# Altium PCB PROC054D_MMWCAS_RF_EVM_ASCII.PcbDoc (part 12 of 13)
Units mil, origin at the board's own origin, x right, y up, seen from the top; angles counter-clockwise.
Board outline 6299.21 x 5370.07 mil, 8 copper layers (L1 TOP, L2 GND, L3 SIGNAL 1, L4 GND, L5 SIGNAL 2, L6 SIGNAL 3, L7 GND, L8 BOTTOM), stack 53.5 mil thick; 775 components, 552 nets, 2648 pads, 7845 vias.
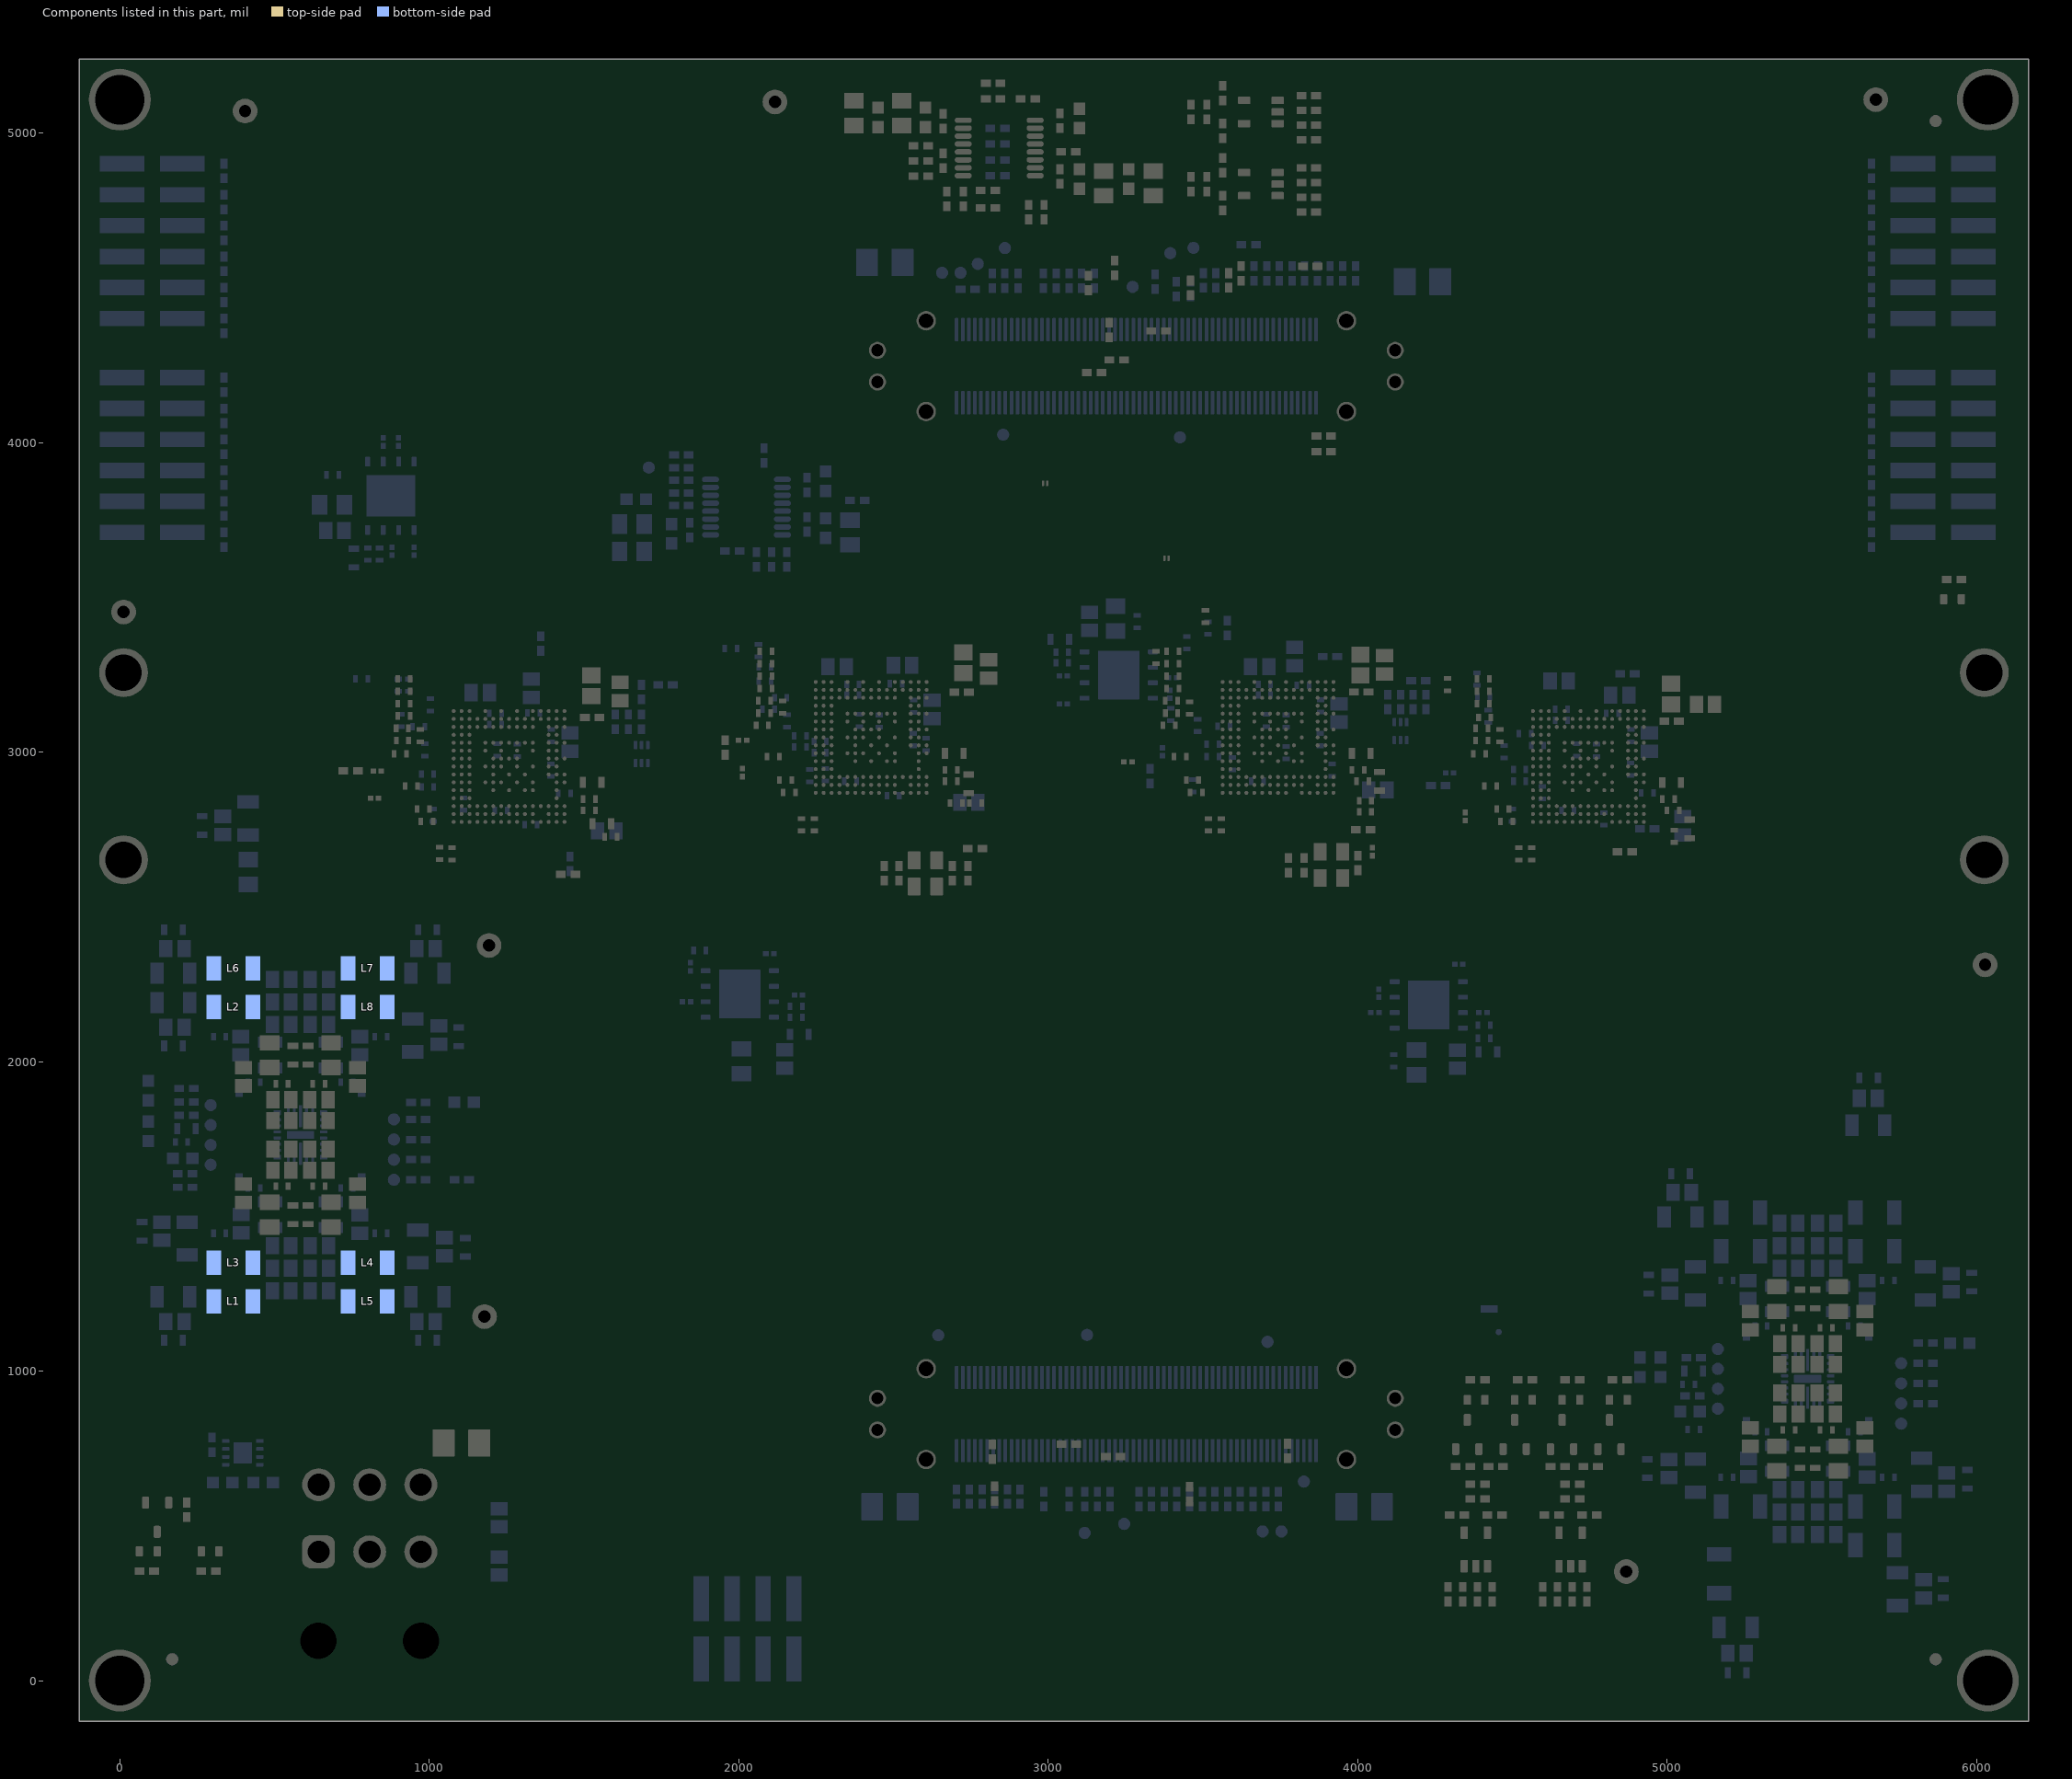
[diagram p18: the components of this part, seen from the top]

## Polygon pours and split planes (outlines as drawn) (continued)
AWR_4_1V2_FILT on L8 BOTTOM "L8_BOTTOM_AWR_4_1V2_FILT_P29790" (solid, remove dead copper, pour order 29790): 19 vertices, not listed, extent -131.11,1296.94 332.13,3060.36
AWR_4_1V8_FILT on L8 BOTTOM "L8_BOTTOM_AWR_4_1V8_FILT_P29702" (solid, remove dead copper, pour order 29702): 1314.48,3068.75 1283.95,3099.27 1283.95,3185.88 1297.79,3199.72 1357.07,3199.72 1360.98,3195.82 1360.98,3156.42 1356.01,3151.45 1340.03,3151.45 1328.67,3140.09 1328.67,3082.94 1316.61,3070.88
AWR_3_1V8_FILT on L8 BOTTOM "L8_BOTTOM_AWR_3_1V8_FILT_P29703" (solid, remove dead copper, pour order 29703): 3799.3,3157.94 3799.3,3160.31 3764.59,3195.02 3764.59,3296.99 3768.63,3301.03 3817.76,3301.03 3824.31,3294.48 3824.31,3174.4 3808.57,3158.65
LMK2_3V3 on L8 BOTTOM "L8_BOTTOM_LMK2_3V3_P29704" (solid, remove dead copper, pour order 29704): 1985.94,3661.24 2019.56,3661.24 2021.37,3659.44 2021.37,3627.32 2032.47,3616.21 2066.39,3616.21 2070.9,3611.71 2070.9,3549.27 2068.19,3546.56 2002.15,3546.56 1982.34,3566.38 1982.34,3657.85 1985.51,3661.02
PMIC1_SW_B1 on L8 BOTTOM "L8_BOTTOM_PMIC1_SW_B1_P29708" (solid, remove dead copper, pour order 29708): 564.74,1621.53 540.48,1597.27 540.48,1534.8 531.2,1525.51 446.86,1525.51 441.43,1530.95 441.43,1600.06 444.98,1603.62 526.25,1603.62 564.74,1642.11
PMIC2_SW_B3 on L8 BOTTOM "L8_BOTTOM_PMIC2_SW_B3_P29711" (solid, remove dead copper, pour order 29711): 5435.47,1116.54 5411.21,1140.8 5411.21,1203.27 5401.92,1212.56 5317.59,1212.56 5312.15,1207.12 5312.15,1138 5315.71,1134.45 5396.98,1134.45 5435.47,1095.96
PMIC1_SW_B3 on L8 BOTTOM "L8_BOTTOM_PMIC1_SW_B3_P29709" (solid, remove dead copper, pour order 29709): 564.74,1904.39 540.48,1928.65 540.48,1991.13 531.2,2000.41 446.86,2000.41 441.43,1994.97 441.43,1925.86 444.98,1922.3 526.25,1922.3 564.74,1883.81
PMIC2_SW_B1 on L8 BOTTOM "L8_BOTTOM_PMIC2_SW_B1_P29707" (solid, remove dead copper, pour order 29707): 5435.47,833.68 5411.21,809.41 5411.21,746.94 5401.92,737.66 5317.59,737.66 5312.15,743.09 5312.15,812.21 5315.71,815.77 5396.98,815.77 5435.47,854.26
SYSTEM_3V3 on L8 BOTTOM "L8_BOTTOM_SYSTEM_3V3_P29713" (solid, remove dead copper, pour order 29713): 4119.08,1929.88 4150.24,1961.04 4150.24,1978.85 4161.13,1989.74 4225.69,1989.74 4230.89,1984.54 4230.89,1919.98 4211.1,1900.19 4127.03,1900.19 4119.08,1908.13
SYSTEM_3V3 on L8 BOTTOM "L8_BOTTOM_SYSTEM_3V3_P29714" (solid, remove dead copper, pour order 29714): 1655.67,3304.32 1655.67,3252.4 1673.06,3235.01 1673.06,3202.27 1676.13,3199.2 1751.58,3199.2 1757.72,3205.34 1757.72,3267.24 1716.4,3308.55 1659.81,3308.55 1655.72,3304.45
GND on L8 BOTTOM "L8_BOTTOM_GND_P29716" (solid, remove dead copper, pour order 29716): 2520.71,3233.05 2536.96,3249.29 2536.96,3308.95 2546.24,3318.24 2546.24,3337.25 2562.13,3353.13 2624.56,3353.13 2644,3333.69 2644,3286.65 2635.37,3278.02 2604.61,3278.02 2583.1,3256.51 2583.1,3235.11 2557,3209.01 2520.5,3209.01
AWR_1_1V0_RF2_FILT on L8 BOTTOM "L8_BOTTOM_AWR_1_1V0_RF2_FILT_P29722" (solid, remove dead copper, pour order 29722): 2575.22,3152.32 2566.3,3143.41 2518.78,3143.41 2509.79,3152.4 2509.79,3178.83 2528.38,3197.42 2565.14,3197.42 2593.02,3225.31 2593.02,3244.09 2611.23,3262.29 2666.34,3262.29 2672.43,3256.19 2672.43,3162.3 2662.35,3152.22
GND on L8 BOTTOM "L8_BOTTOM_GND_P29723" (solid, remove dead copper, pour order 29723): 19 vertices, not listed, extent 4830.85,3112.64 4957.73,3269.52
GND on L8 BOTTOM "L8_BOTTOM_GND_P29718" (solid, remove dead copper, pour order 29718): 17 vertices, not listed, extent 324.94,1863.73 435.27,2042.6
GND on L8 BOTTOM "L8_BOTTOM_GND_P29724" (solid, remove dead copper, pour order 29724): 55.37,1459.42 253.34,1459.39 262.11,1468.17 262.11,1516.41 251.59,1526.93 60.99,1526.93 51.3,1517.25 51.3,1463.49
GND on L8 BOTTOM "L8_BOTTOM_GND_P29726" (solid, remove dead copper, pour order 29726): 2310.48,3305.51 2310.48,3241.04 2325.47,3226.05 2341.84,3226.05 2350.84,3217.05 2350.84,3172.19 2241.17,3172.19 2214.62,3198.73 2214.62,3269.85 2259.77,3315 2300.99,3315
GND on L8 BOTTOM "L8_BOTTOM_GND_P29727" (solid, remove dead copper, pour order 29727): 1156.54,3219.67 1156.54,3162.35 1180.32,3138.57 1200.5,3138.57 1202.77,3136.3 1202.77,3076.8 1201.25,3075.29 1104.24,3075.29 1056.16,3123.38 1056.16,3167.32 1080.46,3191.62 1082.27,3191.62 1114.17,3223.53 1152.74,3223.53 1156.46,3219.81
GND on L8 BOTTOM "L8_BOTTOM_GND_P29728" (solid, remove dead copper, pour order 29728): 2743.43,2912.56 2743.43,2973.73 2774.02,3004.31 2793.61,3004.31 2827.53,2970.38 2827.53,2822.73 2808.42,2803.61 2753.95,2803.61 2743.42,2814.15 2743.42,2911.89
GND on L8 BOTTOM "L8_BOTTOM_GND_P29729" (solid, remove dead copper, pour order 29729): 5125.26,693.18 4922.11,693.06 4905.82,709.34 4905.82,748.12 4924.74,767.04 5112.73,767.04 5130.98,748.79 5130.98,698.9
GND on L8 BOTTOM "L8_BOTTOM_GND_P29730" (solid, remove dead copper, pour order 29730): 4049.36,427.21 4120.73,427.22 4132.64,439.13 4132.64,594.57 4120.07,607.14 4041.41,607.14 4036.71,602.44 4036.71,439.87
GND on L8 BOTTOM "L8_BOTTOM_GND_P29731" (solid, remove dead copper, pour order 29731): 2304.82,524.41 2304.82,603.47 2316.8,615.44 2463.57,615.44 2471.61,607.41 2471.61,519.68 2462.83,510.9 2318.33,510.9
GND on L8 BOTTOM "L8_BOTTOM_GND_P29733" (solid, remove dead copper, pour order 29733): 4644.68,3257.81 4644.68,3093.35 4639.57,3088.24 4553.73,3088.24 4533.76,3108.21 4533.95,3108.4 4533.95,3244.72 4557.27,3268.04 4634.41,3268.04 4644.52,3257.92
GND on L8 BOTTOM "L8_BOTTOM_GND_P29735" (solid, remove dead copper, pour order 29735): 5706.74,287.57 5904.93,287.65 5920.47,272.11 5920.47,228.75 5879.89,188.17 5714.78,188.17 5700.3,202.64 5700.3,281.13
QSPI_FLASH_3V3_3 on L8 BOTTOM "L8_BOTTOM_QSPI_FLASH_3V3_3_P29736" (solid, remove dead copper, pour order 29736): 17 vertices, not listed, extent 3053.43,3275.51 3300.68,3418.57
GND on L8 BOTTOM "L8_BOTTOM_GND_P29737" (solid, remove dead copper, pour order 29737): 251.93,2771.63 429.87,2771.53 457.14,2798.8 457.14,2867.2 450.2,2874.13 266.15,2874.13 239.05,2847.04 239.05,2784.52
GND on L8 BOTTOM "L8_BOTTOM_GND_P29738" (solid, remove dead copper, pour order 29738): 5234.36,197.62 5234.36,11.78 5254.9,-8.76 5315.01,-8.76 5336.05,12.28 5336.05,193.94 5320.82,209.17 5245.78,209.17 5234.47,197.86
GND on L8 BOTTOM "L8_BOTTOM_GND_P29740" (solid, remove dead copper, pour order 29740): 1136.85,1409.74 938.77,1409.74 917.18,1431.33 917.18,1495.24 932,1510.05 1113.99,1510.05 1147.98,1476.06 1147.98,1420.75 1137.01,1409.79
GND on L8 BOTTOM "L8_BOTTOM_GND_P29741" (solid, remove dead copper, pour order 29741): 4920.12,1273.11 5110.12,1273.11 5139.01,1244.22 5139.01,1186.07 5125.3,1172.37 4930.49,1172.37 4910.12,1192.74 4910.12,1263.22 4919.64,1272.74
GND on L8 BOTTOM "L8_BOTTOM_GND_P29742" (solid, remove dead copper, pour order 29742): 169.84,1088.49 169.83,1259.99 149.91,1279.91 67.74,1279.91 56.63,1268.79 56.63,1089.92 75.84,1070.71 152.06,1070.71
GND on L8 BOTTOM "L8_BOTTOM_GND_P29743" (solid, remove dead copper, pour order 29743): 997.21,1077.96 996.89,1266.04 1009.07,1278.22 1099.69,1278.22 1110.42,1267.28 1110.45,1076.9 1104.26,1070.71 1004.45,1070.71
GND on L8 BOTTOM "L8_BOTTOM_GND_P29744" (solid, remove dead copper, pour order 29744): 5040.56,1660.15 5040.56,1460.89 5036.7,1457.04 4930.05,1457.04 4927.35,1459.74 4927.35,1661.16 4933.54,1667.36 5033.35,1667.36
GND on L8 BOTTOM "L8_BOTTOM_GND_P29745" (solid, remove dead copper, pour order 29745): 997.84,2245.26 1005.7,2237.4 1102.59,2237.4 1110.45,2245.26 1110.45,2449.02 1104.26,2455.21 1004.45,2455.21 997.21,2447.97
AWR_1_1V8_FILT on L8 BOTTOM "L8_BOTTOM_AWR_1_1V8_FILT_P29746" (solid, remove dead copper, pour order 29746): 332.13,2222.83 332.13,2138.87 275.33,2082.08 275.33,2041.53 262.7,2028.89 196.29,2028.89 185.13,2040.06 185.13,2216.65 197.47,2228.99 326.01,2228.99 332.08,2222.91
GND on L8 BOTTOM "L8_BOTTOM_GND_P29747" (solid, remove dead copper, pour order 29747): 5643.31,1749.23 5643.31,1960.96 5621.7,1982.57 5556.19,1982.57 5536.6,1962.98 5536.6,1760.04 5555.51,1741.13 5635.11,1741.13 5642.94,1748.96
GND on L8 BOTTOM "L8_BOTTOM_GND_P29748" (solid, remove dead copper, pour order 29748): 907.32,1966.28 896.53,1977.07 896.53,2065.22 910.15,2078.84 1113.28,2078.2 1122.53,2068.95 1122.53,1974.86 1113.96,1966.28
LMK2_3V3 on L8 BOTTOM "L8_BOTTOM_LMK2_3V3_P29734" (solid, remove dead copper, pour order 29734): 2207.97,3730.27 2385.87,3730.27 2455.01,3661.14 2455.01,3649.75 2447.16,3641.91 2227.17,3641.91 2194.37,3674.71 2194.37,3717.72 2206.87,3730.22
AWR_4_1V8_FILT on L8 BOTTOM "L8_BOTTOM_AWR_4_1V8_FILT_P29749" (solid, remove dead copper, pour order 29749): 332.13,2341.49 311.01,2362.61 311.01,2403.27 266.74,2447.53 196.29,2447.53 185.13,2436.37 185.13,2259.78 197.47,2247.44 326.01,2247.44 332.08,2253.52
QSPI_FLASH_3V3_2 on L8 BOTTOM "L8_BOTTOM_QSPI_FLASH_3V3_2_P29739" (solid, remove dead copper, pour order 29739): 4108.15,2009.8 4095.5,2022.45 4095.51,2029.36 4128.41,2062.26 4270.24,2062.26 4329.98,2122 4361.68,2122 4372.82,2133.14 4400.06,2133.14 4403.51,2129.69 4403.51,2015.02 4398.28,2009.8
QSPI_FLASH_3V3_4 on L8 BOTTOM "L8_BOTTOM_QSPI_FLASH_3V3_4_P29750" (solid, remove dead copper, pour order 29750): 696.84,3909.9 704.45,3917.51 762.42,3917.51 774.97,3905.14 774.97,3769.35 813.86,3730.46 813.86,3705.83 852.74,3666.95 852.74,3652.82 841.38,3641.45 729.6,3641.45 696.84,3674.22
GND on L8 BOTTOM "L8_BOTTOM_GND_P29751" (solid, remove dead copper, pour order 29751): 5774.37,1277.94 6003.39,1278.01 6019.4,1261.99 6019.4,1196.69 5990.33,1167.61 5777,1167.61 5757.35,1187.26 5757.35,1260.92
SYSTEM_1V8 on L8 BOTTOM "L8_BOTTOM_SYSTEM_1V8_P29752" (solid, remove dead copper, pour order 29752): 447.57,2756.32 260.56,2756.58 244.13,2740.14 244.13,2676.83 312.92,2608.04 442.59,2608.04 452.18,2617.63 452.18,2751.71
QSPI_FLASH_3V3_1 on L8 BOTTOM "L8_BOTTOM_QSPI_FLASH_3V3_1_P29753" (solid, remove dead copper, pour order 29753): 1905.12,2085.04 1890.62,2070.54 1890.62,2024.38 1901.01,2013.47 2175.27,2013.47 2178.49,2016.69 2178.49,2185.59 2173.48,2190.6 2156.66,2190.6 2132.68,2166.63 2107.28,2166.63 2094.75,2154.1 2094.75,2119.75 2060.04,2085.04
AWR_1_1V2_FILT on L8 BOTTOM "L8_BOTTOM_AWR_1_1V2_FILT_P29754" (solid, remove dead copper, pour order 29754): 332.08,1272.41 332.17,1109.48 301.07,1078.39 196.29,1078.39 185.13,1089.56 185.13,1266.14 197.47,1278.48 326.01,1278.48
GND on L8 BOTTOM "L8_BOTTOM_GND_P29755" (solid, remove dead copper, pour order 29755): 5990.27,651.02 5799.61,650.95 5780.88,669.68 5780.88,783.52 5792.5,795.15 5952.19,795.15 5993.37,753.96 5993.37,654.12
GND on L8 BOTTOM "L8_BOTTOM_GND_P29756" (solid, remove dead copper, pour order 29756): 19 vertices, not listed, extent 2371.03,2979.69 2664.08,3136.04
GND on L8 BOTTOM "L8_BOTTOM_GND_P29758" (solid, remove dead copper, pour order 29758): 24 vertices, not listed, extent 5401.32,434.32 5506.97,814.79
GND on L8 BOTTOM "L8_BOTTOM_GND_P29759" (solid, remove dead copper, pour order 29759): 24 vertices, not listed, extent 5401.32,1135.43 5506.97,1515.89
GND on L8 BOTTOM "L8_BOTTOM_GND_P29761" (solid, remove dead copper, pour order 29761): 24 vertices, not listed, extent 530.59,1222.18 636.24,1602.64
AWR_1_1V0_RF1_FILT on L8 BOTTOM "L8_BOTTOM_AWR_1_1V0_RF1_FILT_P29762" (solid, remove dead copper, pour order 29762): 841.37,1393.48 1188.05,1393.48 1196.55,1384.98 1196.55,1304.55 1188.94,1296.94 841.07,1296.94 835,1303.01 834.95,1387.06
AWR_2_1V0_RF2_FILT on L8 BOTTOM "L8_BOTTOM_AWR_2_1V0_RF2_FILT_P29763" (solid, remove dead copper, pour order 29763): 5741.9,635.42 5985.12,635.42 5990.14,630.4 5990.14,534.13 5965.09,509.08 5711.8,509.08 5705.72,515.16 5705.67,515.24 5705.67,599.2
AWR_2_1V0_RF1_FILT on L8 BOTTOM "L8_BOTTOM_AWR_2_1V0_RF1_FILT_P29764" (solid, remove dead copper, pour order 29764): 5724.3,302.96 5900.66,302.96 5913.24,315.54 5913.24,417.72 5840.33,490.63 5711.8,490.63 5705.72,484.55 5705.63,321.63
AWR_3_1V8_FILT on L8 BOTTOM "L8_BOTTOM_AWR_3_1V8_FILT_P29765" (solid, remove dead copper, pour order 29765): 5129.82,1288.65 4927.22,1288.65 4916.02,1299.85 4916.02,1393.14 4950.21,1427.33 5186.95,1427.33 5197.81,1416.57 5197.81,1356.64
AWR_1_1V0_RF1_FILT on L8 BOTTOM "L8_BOTTOM_AWR_1_1V0_RF1_FILT_P29769" (solid, remove dead copper, pour order 29769): 22 vertices, not listed, extent 2212.61,3117.64 2472.16,3467.22
GND on L8 BOTTOM "L8_BOTTOM_GND_P29768" (solid, remove dead copper, pour order 29768): 18 vertices, not listed, extent 4635.94,2850.72 4978.96,3027.83
GND on L8 BOTTOM "L8_BOTTOM_GND_P29770" (solid, remove dead copper, pour order 29770): 169.87,2447.97 168.54,2026.3 159.29,2017.05 101.92,2017.05 56.63,2062.34 56.63,2403.84 108,2455.21 162.62,2455.21
PMIC2_AWR_23_1V8 on L8 BOTTOM "L8_BOTTOM_PMIC2_AWR_23_1V8_P29773" (solid, remove dead copper, pour order 29773): 5229.84,1539.43 5258.28,1567.87 5367.3,1567.87 5387.93,1546.73 5387.93,1297.59 5398.74,1286.78 5398.74,1259.08 5395.9,1256.24 5316.28,1256.23 5302.31,1270.2 5234.17,1270.2 5229.84,1274.53
PMIC2_AWR_2_1V0 on L8 BOTTOM "L8_BOTTOM_PMIC2_AWR_2_1V0_P29774" (solid, remove dead copper, pour order 29774): 5678.68,410.78 5650.25,382.34 5541.23,382.34 5520.59,403.48 5520.59,652.62 5509.78,663.43 5509.78,691.13 5512.62,693.97 5592.25,693.98 5606.22,680.01 5674.36,680.01 5678.68,675.69
PMIC2_AWR_3_1V0 on L8 BOTTOM "L8_BOTTOM_PMIC2_AWR_3_1V0_P29772" (solid, remove dead copper, pour order 29772): 5678.68,1539.43 5650.25,1567.87 5541.23,1567.87 5520.59,1546.73 5520.59,1297.59 5509.78,1286.78 5509.78,1259.08 5512.62,1256.24 5592.25,1256.23 5606.22,1270.2 5674.36,1270.2 5678.68,1274.53
PMIC1_AWR_4_1V0 on L8 BOTTOM "L8_BOTTOM_PMIC1_AWR_4_1V0_P29776" (solid, remove dead copper, pour order 29776): 807.96,2327.29 779.52,2355.73 670.5,2355.73 649.87,2334.59 649.87,2085.45 639.06,2074.63 639.06,2046.94 641.9,2044.1 721.52,2044.09 735.49,2058.06 803.63,2058.06 807.96,2062.38
PMIC1_AWR_1_1V0 on L8 BOTTOM "L8_BOTTOM_PMIC1_AWR_1_1V0_P29775" (solid, remove dead copper, pour order 29775): 807.96,1198.63 779.52,1170.2 670.5,1170.2 649.87,1191.34 649.87,1440.48 639.06,1451.29 639.06,1478.99 641.9,1481.83 721.52,1481.83 735.49,1467.86 803.63,1467.86 807.96,1463.54
PMIC1_AWR_14_1V2 on L8 BOTTOM "L8_BOTTOM_PMIC1_AWR_14_1V2_P29771" (solid, remove dead copper, pour order 29771): 359.12,1198.63 387.55,1170.2 496.57,1170.2 517.21,1191.34 517.21,1440.48 528.02,1451.29 528.02,1478.99 525.18,1481.83 445.55,1481.83 431.58,1467.86 363.44,1467.86 359.12,1463.54
PMIC2_AWR_23_1V2 on L8 BOTTOM "L8_BOTTOM_PMIC2_AWR_23_1V2_P29777" (solid, remove dead copper, pour order 29777): 17 vertices, not listed, extent 5111.94,382.34 5398.74,693.98
SYSTEM_5V0 on L8 BOTTOM "L8_BOTTOM_SYSTEM_5V0_P29779" (solid, remove dead copper, pour order 29779): 385.39,1155.02 781.54,1155.09 800.07,1136.57 800.07,1028.87 786.7,1015.5 384.6,1015.5 368.88,1031.23 368.88,1138.51
SYSTEM_5V0 on L8 BOTTOM "L8_BOTTOM_SYSTEM_5V0_P29780" (solid, remove dead copper, pour order 29780): 5256.11,1722.32 5652.26,1722.39 5670.79,1703.87 5670.79,1596.17 5657.43,1582.8 5255.33,1582.8 5239.6,1598.53 5239.6,1705.81
SYSTEM_5V0 on L8 BOTTOM "L8_BOTTOM_SYSTEM_5V0_P29778" (solid, remove dead copper, pour order 29778): 5256.11,367.16 5652.26,367.24 5670.79,348.71 5670.79,241.01 5657.43,227.65 5255.33,227.65 5239.6,243.37 5239.6,350.65
AWR_2_1V0_RF1_FILT on L8 BOTTOM "L8_BOTTOM_AWR_2_1V0_RF1_FILT_P29781" (solid, remove dead copper, pour order 29781): 4696.06,3074.55 4659.12,3111.49 4659.12,3260.66 4601.6,3318.18 4601.6,3490.74 4639.94,3529.09 4784.44,3529.09 4805.49,3508.04 4805.49,3411.24 4744.23,3349.98 4744.23,3058.09 4735.84,3049.7 4721.04,3049.7 4696.87,3073.87
PMIC1_AWR_14_1V8 on L8 BOTTOM "L8_BOTTOM_PMIC1_AWR_14_1V8_P29783" (solid, remove dead copper, pour order 29783): 18 vertices, not listed, extent 293.69,2044.09 528.02,2599.17
AWR_1_1V8_FILT on L8 BOTTOM "L8_BOTTOM_AWR_1_1V8_FILT_P29786" (solid, remove dead copper, pour order 29786): 2733.3,3018.37 2733.3,2986.35 2733.3,2693.85 2688.04,2648.59 2422.22,2648.59 2326.04,2744.77 2326.04,2941.5 2353.94,2968.94 2544.94,2968.94 2594.37,3018.37
AWR_1_1V8_FILT on L8 BOTTOM "L8_BOTTOM_AWR_1_1V8_FILT_P29732" (solid, remove dead copper, pour order 29732): 2457.74,3437.82 2466.79,3446.87 2539.89,3446.87 2548.77,3437.81 2548.77,3407.34 2530.87,3389.44 2530.87,3330.91 2521.89,3321.94 2521.89,3255.09 2505.24,3238.43 2505.24,3190.24 2488.85,3173.85 2457.74,3204.97
AWR_2_1V2_FILT on L8 BOTTOM "L8_BOTTOM_AWR_2_1V2_FILT_P29787" (solid, remove dead copper, pour order 29787): 23 vertices, not listed, extent 4545.61,495.57 5202.85,1325.64
SYSTEM_5V0 on L8 BOTTOM "L8_BOTTOM_SYSTEM_5V0_P29791" (solid, remove dead copper, pour order 29791): 24 vertices, not listed, extent 2487.38,46.76 4021.69,783.63
GND on L8 BOTTOM "L8_BOTTOM_GND_P29767" (solid, remove dead copper, pour order 29767): 18 vertices, not listed, extent 1184.59,2879.45 1492.81,3042.1
GND on L8 BOTTOM "L8_BOTTOM_GND_P29766" (solid, remove dead copper, pour order 29766): 3649.25,3104.96 3649.25,3049.61 3702.98,2995.88 3911.78,2995.88 3977.42,3061.52 3977.42,3110.01 3968.87,3118.56 3662.85,3118.56
SYSTEM_3V3 on L8 BOTTOM "L8_BOTTOM_SYSTEM_3V3_P29715" (solid, remove dead copper, pour order 29715): 312.14,611.67 223.07,611.67 209.27,625.47 209.27,683.1 227.78,701.61 236.86,701.61 353.82,701.61 353.89,692 342.2,680.32 331.61,680.32 321.28,669.99 321.28,620.81
GND on L8 BOTTOM "L8_BOTTOM_GND_P29717" (solid, remove dead copper, pour order 29717): 377.44,716.09 369.17,707.82 369.17,684.67 342.1,657.59 342.1,594.18 355.44,580.84 437.95,580.84 452.35,595.24 452.35,658.52 424.84,686.04 424.84,708.06 416.81,716.09
AWR_3_1V2_FILT on L8 BOTTOM "L8_BOTTOM_AWR_3_1V2_FILT_P29784" (solid, remove dead copper, pour order 29784): 3415,2926.83 3522.31,3034.14 3632.94,3034.14 3688.8,2978.27 3796.08,2978.27 3816.09,2958.26 3816.09,2796.64 3710.44,2690.99 3475.55,2690.99 3415,2751.55
SYSTEM_5V0 on L8 BOTTOM "L8_BOTTOM_SYSTEM_5V0_P29757" (solid, remove dead copper, pour order 29757): 18 vertices, not listed, extent 440.48,612.88 715.24,828.57
SYSTEM_3V3 on L3 SIGNAL 1 "L3_SIGNAL_1_SYSTEM_3V3_P29682" (solid, remove dead copper, pour order 29682): 19 vertices, not listed, extent 2819,3443.85 6168.77,5235.17
AWR_3_1V2_FILT on L3 SIGNAL 1 "L3_SIGNAL_1_AWR_3_1V2_FILT_P29678" (solid, remove dead copper, pour order 29678): 4005.77,1049.26 3933.6,977.08 3443.92,977.08 3238.07,1181.62 3238.07,1884.53 3238.07,2920.34 3282.12,2964.39 3458.65,3140.84 3651.28,3140.84 3798.48,2993.64 3798.48,1309.59 4005.77,1102.29
SYSTEM_3V3 on L3 SIGNAL 1 "L3_SIGNAL_1_SYSTEM_3V3_P29675" (solid, remove dead copper, pour order 29675): 4243.58,239.65 5079.35,239.61 5228.42,388.68 5993.24,388.68 6020.97,416.42 6020.97,978.39 6000.72,998.64 5897.16,998.64 5883.55,985.03 5883.55,761.72 5790.91,669.08 4284.49,669.08 4216.52,601.11 4216.52,266.71
AWR_1_1V8_FILT on L3 SIGNAL 1 "L3_SIGNAL_1_AWR_1_1V8_FILT_P29677" (solid, remove dead copper, pour order 29677): 33 vertices, not listed, extent 219.24,2018.28 2602.93,3521.26
AWR_4_1V8_FILT on L3 SIGNAL 1 "L3_SIGNAL_1_AWR_4_1V8_FILT_P29674" (solid, remove dead copper, pour order 29674): 33 vertices, not listed, extent 229.3,2334.58 1604.42,3118.67
SYSTEM_1V8 on L3 SIGNAL 1 "L3_SIGNAL_1_SYSTEM_1V8_P29681" (solid, remove dead copper, pour order 29681): 3338.64,4707.22 2888.04,4707.22 2887.04,4706.22 1925.24,4706.22 646.35,4706.22 644.69,4707.22 621.9,4730 621.9,4890.17 965.5,5233.76 3248.9,5233.76 3382.4,5100.27 3382.4,4750.97
AWR_2_1V2_FILT on L3 SIGNAL 1 "L3_SIGNAL_1_AWR_2_1V2_FILT_P29680" (solid, remove dead copper, pour order 29680): 4194.59,1669.78 4639.62,1224.75 4833.81,1224.75 4948.3,1338.9 4948.3,3000.29 4739.1,3209.49 4264.45,3209.49 4194.59,3139.64
AWR_4_1V2_FILT on L3 SIGNAL 1 "L3_SIGNAL_1_AWR_4_1V2_FILT_P29679" (solid, remove dead copper, pour order 29679): 26 vertices, not listed, extent -127.34,1294.53 1171.02,3439.25
AWR_1_1V0_RF2_FILT on L3 SIGNAL 1 "L3_SIGNAL_1_AWR_1_1V0_RF2_FILT_P29676" (solid, remove dead copper, pour order 29676): 1503.23,627.05 1464.92,665.36 1464.92,753.57 2246.94,1535.59 2757.85,1535.59 2822.27,1471.17 2822.27,709.1 2740.22,627.05
PMIC2_3V3 on L3 SIGNAL 1 "L3_SIGNAL_1_PMIC2_3V3_P29673" (solid, remove dead copper, pour order 29673): 19 vertices, not listed, extent 4858.79,683.99 5874.61,1146.4
AWR_1_1V2_FILT on L3 SIGNAL 1 "L3_SIGNAL_1_AWR_1_1V2_FILT_P29683" (solid, remove dead copper, pour order 29683): 38 vertices, not listed, extent -132.18,237.72 2611.83,3138.94
no net on Top Solder "Top Solder-No Net" (solid, pour order 29799): 3332.36,3390.31 3432.91,3390.31 3432.91,3495.97 3446.81,3509.87 3446.81,3605.94 3491.24,3650.37 3530.36,3650.37 3530.36,3735.15 3233.36,3735.15 3233.36,3648.77 3275.61,3648.77 3316.33,3608.05 3316.33,3520.34 3332.36,3504.31 3332.36,3390.31
no net on Top Solder "Top Solder-No Net" (solid, pour order 29801): 67 vertices, not listed, extent 3614,3123.04 5771.11,5188
no net on Top Solder "Top Solder-No Net" (solid, pour order 29803): 146 vertices, not listed, extent 1312.4,1032 5351,3172.49
GND on Top Solder "Top Solder-No Net" (solid, pour order 29802): 66 vertices, not listed, extent 600,3123.04 2718,5188
no net on Top Solder "Top Solder-No Net" (solid, pour order 29800): 2940,3623.5 3040.55,3623.5 3040.55,3737.98 3054.45,3751.88 3054.45,3847.95 3098.88,3892.38 3138,3892.38 3138,3977.16 2841,3977.16 2841,3890.78 2883.25,3890.78 2923.97,3850.06 2923.97,3762.35 2940,3746.32 2940,3623.5
AWR_1_1V0_RF1_FILT on L5 SIGNAL 2 "L5_SIGNAL_2_AWR_1_1V0_RF1_FILT_P29689" (solid, remove dead copper, pour order 29689): 27 vertices, not listed, extent 1117.03,1258.71 2672.13,3484.42
GND on L5 SIGNAL 2 "L5_SIGNAL_2_GND_P29692" (solid, remove dead copper, pour order 29692): -131,-131 6168.21,-131 6168.21,5239.07 -131,5239.07
SYSTEM_3V3 on L5 SIGNAL 2 "L5_SIGNAL_2_SYSTEM_3V3_P29691" (solid, remove dead copper, pour order 29691): 188 vertices, not listed, extent -131,-131 5930.08,5238.71
AWR_2_1V0_RF2_FILT on L5 SIGNAL 2 "L5_SIGNAL_2_AWR_2_1V0_RF2_FILT_P29688" (solid, remove dead copper, pour order 29688): 17 vertices, not listed, extent 5222.4,486.7 6164.28,2979.58
AWR_3_1V8_FILT on L5 SIGNAL 2 "L5_SIGNAL_2_AWR_3_1V8_FILT_P29690" (solid, remove dead copper, pour order 29690): 23 vertices, not listed, extent 3471.79,1035.43 5014.03,3258.13
AWR_2_1V0_RF1_FILT on L5 SIGNAL 2 "L5_SIGNAL_2_AWR_2_1V0_RF1_FILT_P29687" (solid, remove dead copper, pour order 29687): 5207.33,2501.24 5207.33,2455.45 5594.88,2067.91 5594.88,1991.57 5521.99,1918.68 4789.47,1918.68 4688.92,2017.98 4688.92,2235.08 4688.92,3512.52 4715.23,3538.84 4780.41,3538.84 5207.33,3111.92 5207.33,2592.86
SYSTEM_3V3 on L5 SIGNAL 2 "L5_SIGNAL_2_SYSTEM_3V3_P29686" (solid, remove dead copper, pour order 29686): 48 vertices, not listed, extent 3003,2913.21 4375.6,4618.88
AWR_4_1V8_FILT on L5 SIGNAL 2 "L5_SIGNAL_2_AWR_4_1V8_FILT_P29685" (solid, remove dead copper, pour order 29685): 1483.42,2743.92 1516.67,2777.17 1516.67,2997.47 1407.92,3107.62 1406.07,3109.48 1405.21,3108.63 1123.12,3108.63 1084.91,3070.42 1084.91,2812.77 1153.77,2743.92
AWR_3_1V2_FILT on L6 SIGNAL 3 "L6_SIGNAL_3_AWR_3_1V2_FILT_P29697" (solid, remove dead copper, pour order 29697): 3456.69,3146.71 3456.69,2997.69 3415,2956 3415,2747.99 3486.3,2676.69 3796.7,2676.69 3844,2723.99 3844,3024.66 3718.66,3150 3487,3150
SYSTEM_1V8 on L6 SIGNAL 3 "L6_SIGNAL_3_SYSTEM_1V8_P29699" (solid, remove dead copper, pour order 29699): 699.62,4851.17 740.01,4810.77 740.01,4218.05 394.02,3872.06 394.02,2608.2 356.97,2571.15 -112.55,2571.15 -122.82,2581.41 -122.82,4126.55 601.8,4851.17
AWR_1_1V0_RF2_FILT on L6 SIGNAL 3 "L6_SIGNAL_3_AWR_1_1V0_RF2_FILT_P29698" (solid, remove dead copper, pour order 29698): 2579.23,2950.74 2448.05,2819.56 2448.05,2474.21 2746.53,2175.12 2746.53,1290.34 2775.41,1261.46 3040.55,1261.46 3093.57,1314.48 3093.57,2473.6 2846.3,2720.87 2846.3,3219.22 2797.24,3268.28 2620.87,3268.28 2579.23,3226.64
AWR_1_1V8_FILT on L6 SIGNAL 3 "L6_SIGNAL_3_AWR_1_1V8_FILT_P29695" (solid, remove dead copper, pour order 29695): 2360.09,3200.58 2360.09,3385.41 2414.88,3440.21 2556.75,3440.21 2583,3413.95 2583,3260.01 2562.24,3239.25 2562.24,2955.31 2506.78,2899.85 2352.31,2899.85 2320.99,2931.17 2320.99,3161.49
AWR_4_1V8_FILT on L6 SIGNAL 3 "L6_SIGNAL_3_AWR_4_1V8_FILT_P29693" (solid, remove dead copper, pour order 29693): 1150.99,3079.99 1219.62,3148.62 1349.56,3148.62 1409.71,3088.46 1409.71,2833.69 1394,2817.98 1185.56,2817.98 1150.99,2852.55
AWR_2_1V2_FILT on L6 SIGNAL 3 "L6_SIGNAL_3_AWR_2_1V2_FILT_P29694" (solid, remove dead copper, pour order 29694): 4660.57,2646 4690.73,2676.15 4690.73,2945.36 4562.97,3073.12 4446.88,3073.12 4423.38,3049.63 4423.38,2688.31 4465.69,2646
AWR_2_1V8_FILT on L6 SIGNAL 3 "L6_SIGNAL_3_AWR_2_1V8_FILT_P29696" (solid, remove dead copper, pour order 29696): 4684.4,2807.14 4684.4,2862.48 4671.94,2874.94 4671.94,3022.89 4643.09,3051.75 4643.09,3107.75 4713.9,3178.56 4946.18,3178.56 5038.95,3085.78 5038.95,2787.87 4975.87,2724.79 4766.75,2724.79
SYSTEM_5V0 on L6 SIGNAL 3 "L6_SIGNAL_3_SYSTEM_5V0_P29700" (solid, remove dead copper, pour order 29700): 49 vertices, not listed, extent -129.36,-130.66 6168.33,5239.22
GND on L2 GND "L2_GND_GND_P29672" (solid, remove dead copper, pour order 29672): -131,-131 6168.21,-131 6168.21,5239.07 -131,5239.07
GND on L4 GND "L4_GND_GND_P29684" (solid, remove dead copper, pour order 29684): -131,-131 6168.21,-131 6168.21,5239.07 -131,5239.07
GND on L7 GND "L7_GND_GND_P29701" (solid, remove dead copper, pour order 29701): -131,-131 6168.21,-131 6168.21,5239.07 -131,5239.07

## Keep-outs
L2 GND:
  circle w1: c4899.43,2953.5 r6.17
  circle w1: c4899.44,3004.68 r6.17
  circle w1: c4899.43,3055.86 r6.17
  circle w1: c4797.07,3107.04 r6.17
  circle w1: c4745.89,3107.04 r6.17
  circle w1: c4694.71,3107.04 r6.17
  circle w1: c4643.53,3107.04 r6.17
  circle w1: c3896.43,3047.5 r6.17
  circle w1: c3896.43,3098.68 r6.17
  circle w1: c3896.43,3149.86 r6.17
  circle w1: c3794.07,3201.04 r6.17
  circle w1: c3742.89,3201.04 r6.17
  circle w1: c3691.71,3201.04 r6.17
  circle w1: c3640.53,3201.04 r6.17
  circle w1: c2581.43,3047.5 r6.17
  circle w1: c2581.43,3098.68 r6.17
  circle w1: c2581.43,3149.86 r6.17
  circle w1: c2479.07,3201.04 r6.17
  circle w1: c2427.89,3201.04 r6.17
  circle w1: c2376.71,3201.04 r6.17
  circle w1: c2325.53,3201.04 r6.17
  circle w1: c1411.43,2953.5 r6.17
  circle w1: c1411.43,3004.68 r6.17
  circle w1: c1411.43,3055.86 r6.17
  circle w1: c1309.07,3107.04 r6.17
  circle w1: c1257.89,3107.04 r6.17
  circle w1: c1206.71,3107.04 r6.17
  circle w1: c1155.53,3107.04 r6.17
  circle w1: c1411.43,3236 r18.5
  circle w1: c2583,3374.01 r18.5
  circle w1: c3896.43,3374 r18.5
L4 GND:
  circle w1: c2583,3374.01 r18.5
  circle w1: c1411.43,3236 r18.5
  circle w1: c3896.43,3374 r18.5
L5 SIGNAL 2:
  circle w1: c2583,3374.01 r18.5
  circle w1: c1411.43,3236 r18.5
  circle w1: c3896.43,3374 r18.5
L6 SIGNAL 3:
  circle w1: c2583,3374.01 r18.5
L7 GND:
  circle w1: c2583,3374.01 r18.5
  circle w1: c1411.43,3236 r18.5
  circle w1: c3896.43,3374 r18.5
L8 BOTTOM:
  circle w1: c2583,3374.01 r18.5
  circle w1: c1411.43,3236 r18.5
  circle w1: c3896.43,3374 r18.5
Keep-Out Layer:
  circle w1: c0,5108 r110
  circle w1: c0,0 r110
  circle w1: c6037,0 r110
  circle w1: c6037,5108 r110
  circle w1: c12,3257 r90
  circle w1: c12,2652 r90
  circle w1: c642.01,128.84 r90
  circle w1: c972.72,128.84 r90
  circle w1: c6025.21,3257 r90
  circle w1: c6025.21,2652 r90
  lines w10: -136,-131 ccw(c-131,-131) -131,-136 6168.21,-136 ccw(c6168.21,-131) 6173.21,-131 6173.21,5239.07 ccw(c6168.21,5239.07) 6168.21,5244.07 -131,5244.07 ccw(c-131,5239.07) -136,5239.07 -136,-131
  text ".Layer_Name" at 446,-989.49 h60

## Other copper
L1 TOP:
  rectangle net AWR_1_FMCW_CLKOUT: 3376.84,3504.57 3388.1,3529.57
  rectangle net AWR_1_FMCW_SYNCOUT: 2984.48,3756.64 2995.74,3771.58
  text "1" at 1257.24,7.47 h65
  text ".Layer_Name" at 446,-989.49 h60
L2 GND:
  text "2" at 1249.65,6.63 h65
  text ".Layer_Name" at 445.07,-990.08 h60
L3 SIGNAL 1:
  text "3" at 1250.07,8.31 h65
  text ".Layer_Name" at 445.07,-990.08 h60
L4 GND:
  text "4" at 1249.65,7.05 h65
  text ".Layer_Name" at 445.07,-990.08 h60
L5 SIGNAL 2:
  text "5" at 1250.92,5.78 h65
  text ".Layer_Name" at 445.07,-990.08 h60
L6 SIGNAL 3:
  text "6" at 1253.03,7.89 h65
  text ".Layer_Name" at 445.07,-990.08 h60
L7 GND:
  text "7" at 1253.45,6.63 h65
  text ".Layer_Name" at 445.07,-990.08 h60
L8 BOTTOM:
  text "8" at 1253.45,9.16 h65
  text ".Layer_Name" at 445.07,-990.08 h60

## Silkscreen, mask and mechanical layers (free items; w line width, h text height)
Top Overlay:
  circle w10: c2653.03,3214.87 r1.46
  circle w10: c4962.25,3174.79 r1.46
  circle w10: c3957.11,3272.93 r1.46
  circle w10: c1472.79,3163.76 r1.46
  circle w10: c2532.59,2676.81 r1.46
  circle w10: c3845.29,2701.94 r1.46
  lines w6: 423.04,1781.99 448.5,1781.99 459.36,1792.84 ; 707.72,1792.84 718.57,1781.99 744.04,1781.99 ; 2015.77,3320.92 2043.77,3320.92 ; 2332.34,4938.98 2332.34,4951.39 2342.34,4961.38 2507.13,4961.38 ; 3141.02,5026.48 3188.68,5026.48 3205.92,5043.72 ; 3321.38,3093.5 3328.89,3086 3352,3086 ; 3668.24,2669.54 3675.41,2662.38 3741.82,2662.38 ; 4253.97,1016.98 4468.56,1016.98 4483.38,1002.16 ; 4445.75,3005.98 4445.75,2981.4 4432.68,2968.33 4362.08,2968.33 4347.96,2982.45 4347.96,3242.88 4364.32,3259.24 4443.08,3259.24 4454.64,3247.68 4454.64,3104.4 ; 4748.36,1000.98 4759.62,1012.24 5025.79,1012.24 ; 4899.9,871.66 4923.88,871.66 5036.32,759.22 5162.34,759.22 5174.84,771.72 5174.84,792.62 ; 2757.71,3485.51 2859.11,3384.1 3057.1,3384.1 3091.09,3418.09 3091.09,3570.29 3044.01,3617.38 2788.24,3617.38 2757.71,3586.85 2757.71,3485.51
  lines w6.01: 426.48,1732.27 450.83,1732.27 458.48,1724.62 ; 712.07,1737.99 720.84,1746.76 745.04,1746.76 ; 944.93,2996.07 982.13,2996.07 ; 1588.31,2920.15 1615.44,2893.02 1615.44,2758.19 1608.54,2751.29 ; 1625.3,3265.7 1625.3,3335.38 ; 1700.48,3384.1 1672.91,3356.53 1672.91,3172.93 1714.14,3131.7 1818.56,3131.7 1820.77,3131.7 ; 2113.51,3089.5 2157.08,3089.5 ; 2362.29,2651.87 2367.65,2657.23 2439.92,2657.23 ; 2403.8,2681.69 2410.79,2674.7 2496.54,2674.7 2515.65,2693.81 2667,2693.81 2681.98,2678.83 ; 2782.25,3010.69 2821.68,2971.25 2821.68,2844.48 2809.07,2831.87 ; 2786.12,3188.29 2842.17,3188.29 2856.1,3202.22 ; 3388.4,5126.8 3395.26,5133.65 3461.14,5133.65 3467.51,5127.29 ; 3859.81,2776.51 3897.55,2776.51 3958.94,2715.13 4017.83,2715.13 4023.22,2709.74 ; 3990.71,2828.22 3990.71,2786.03 3994.09,2782.65 4070.23,2782.65 4083.47,2795.89 4083.47,2851.3 ; 4965.85,2874.04 4965.85,2814.9 4976.87,2803.88 4976.87,2663.86 5000.58,2640.15 5050.13,2640.15 5086.72,2676.74 ; 5075.6,3098.77 5179.97,3098.77 5190.57,3109.37 ; 5080.41,3214.2 5177.07,3214.2 5184.64,3214.2 5191.66,3207.18 ; 5179.7,3099.94 5180.5,3099.94 5197.24,3116.68 ; 5308.53,994.3 5323.35,994.3 5332.39,1003.34 ; 5308.93,959.38 5327.58,959.38 5336.62,950.34 ; 5578.93,951.25 5587.97,960.29 5611.69,960.29 ; 5579.33,1004.26 5588.37,995.22 5611.41,995.22 ; 3558.04,2536.69 3582.59,2512.13 3582.59,2409.62 3609.6,2382.62 3771.65,2382.62 3817.69,2428.65 3817.69,2545.28 3799.88,2563.08 3764.07,2563.08 3685.68,2641.48 3573.77,2641.48 3558.04,2625.75 3558.04,2536.69 ; 5611.27,2605.83 5636.26,2580.84 5816.72,2580.84 5841.1,2605.21 5841.1,2920.7 5815.33,2946.47 5629.38,2946.47 5611.27,2928.36 5611.27,2605.83
  lines w6.1: 1700.48,3384.1 1827.83,3384.1 1862.51,3349.43 1862.51,3172.05 1822.15,3131.7 1820.77,3131.7 ; 2283.74,4769.46 2283.74,4951.15 2324.41,4991.82 ; 2864.51,4820.27 2889.85,4794.93 2889.85,4733.89 ; 5370.26,2568.68 5370.26,2921.86 5393.9,2945.51 5557.86,2945.51 5575.15,2928.22 5575.15,2572.59 5548.93,2546.37 5392.57,2546.37 5370.26,2568.68
  text "NERROR" at 5864.56,3405.4 h30
  text "A" at 3065.94,3343.26 h30
  text "E" at 4474.86,3226.96 h30
  text "D" at 1790.88,3088.59 h30
  text "E" at 5482.95,2962.08 h30
  text "C" at 3964.79,2848.15 h30
  text "D" at 1582.53,2827.14 h30
  text "A" at 2836.26,2824.62 h30
  text "B" at 4992.45,2589.89 h35
  text "C" at 3520.57,2577.97 h30
  text "B" at 5697.65,2527.19 h35
  text "NRST1" at 5037.95,808.98 h30 r90
  text "NRST4" at 5085.36,807.09 h30 r90
  text "NRST2" at 5132.21,805.65 h30 r90
  text "NRST3" at 5180.48,806.13 h30 r90
  text "3.3V" at -89.1,447.91 h30
  text "5V" at 398.79,446.75 h30
  text "Power" at 372.34,407.16 h30
  text "Power" at -102.79,403.42 h30
  text "mmWave Cascade Radar EVM" at 1450,250 h60
  text "MMWCAS-RF-EVM" at 1450,150 h60
  text "PROC054D" at 1450,50 h60
  text ".Layer_Name" at 446,-989.49 h60
Bottom Overlay:
  circle w6: c2669,1068.58 r9.34
  circle w6: c542.01,423.47 r18.82
  circle w6: c311.73,690.17 r3.11
  lines w6: 277.79,1624 313.68,1624 334.05,1644.36 334.05,1882.26 314.76,1901.55 282.07,1901.55 ; 306.13,2363.74 306.13,2425.26 324.51,2443.64 ; 387.94,1087.03 407.64,1106.72 407.64,1154.69 ; 554.57,2448.13 567.1,2435.6 567.1,2313.29 ; 557.32,1106.96 568.59,1118.23 568.59,1215.51 ; 589.57,1213.58 589.57,1112.55 597.03,1105.09 ; 599.98,2313.29 599.98,2435.6 615.99,2451.62 ; 728.79,1163.91 728.79,1104.24 741.36,1091.67 ; 781.78,2367.49 781.78,2425.26 797.16,2440.64 ; 893.97,1588.83 853.56,1588.83 827.28,1615.11 827.28,1823.54 855.21,1851.47 899.61,1851.47 ; 945.37,3105.47 945.37,3133.19 ; 1244.3,3248.17 1273.25,3219.22 1273.25,3098.6 1264.29,3089.64 1251.2,3089.64 ; 1761.06,3991.09 1734.25,4017.89 1734.25,4191.28 1764.41,4221.43 ; 2548.11,4730.46 2593.13,4685.44 2593.13,4604.4 2626.4,4571.13 ; 2565.68,3188.55 2565.68,3200.84 2590.26,3225.43 2604,3225.43 ; 2694.82,525.06 2694.82,280.21 2732.55,242.48 ; 2831.59,4587.45 2831.59,4719.36 2887.16,4774.93 ; 2885.56,5055.79 2885.56,5097.21 2912.65,5124.29 ; 3769.96,3065.21 3769.96,3053.01 3793.34,3029.63 3793.34,3013.36 3821.81,2984.89 3821.81,2970.65 ; 4026.92,4588.28 4089.13,4650.49 4365.73,4650.49 4462.49,4747.26 4462.49,4794.75 ; 4713.62,3065.03 4713.62,3192.47 4738.96,3217.81 ; 4842.66,3048.72 4851.93,3057.98 4864.15,3057.98 ; 5158.94,840.78 5180.79,840.78 5211.25,871.24 5211.25,1078.76 5185.39,1104.63 5165.84,1104.63 ; 5305.31,273.19 5290.29,288.21 5290.29,391.19 5335.88,436.78 ; 5556.28,1682.51 5565.47,1673.31 5565.47,1519.58 ; 5739.61,1639.65 5749.37,1629.89 5749.37,1587.18 ; 5740.64,800.12 5727.47,800.12 5707.94,819.65 5707.94,1039.67 5729.99,1061.73 5742.92,1061.73 ; 4738.96,3217.81 4738.96,3217.81 ; 1285.67,1325.88 1285.67,1823.89 1349.44,1887.66 1652.96,1887.66 1718.37,1822.25 1718.37,1312.82 1661.22,1255.67 1355.88,1255.67 1285.67,1325.88 ; 1777.23,1306.77 1777.23,1820.65 1842.9,1886.32 2171.26,1886.32 2241.86,1815.73 2241.86,1313.34 2181.11,1252.6 1831.41,1252.6 1777.23,1306.77 ; 2672.45,4449.66 ccw(c2663.12,4449.66) 2672.45,4449.66 ; 4238.74,-20.4 4238.74,443.63 4292.21,497.1 4581.95,497.1 4629.82,449.23 4629.82,-17.03 4587.28,-59.56 4277.91,-59.56 4238.74,-20.4 ; 5311.42,2160.49 5311.42,2563.21 5399.97,2651.75 5770.6,2651.75 5850.11,2572.24 5850.11,2160.49 5796.05,2106.43 5365.48,2106.43 5311.42,2160.49
  lines w6.01: 14.26,1984.82 27.03,1997.59 149.27,1997.59 176.03,1970.83 ; 2400.09,3410.53 2412.18,3398.44 2412.18,3210.34 2403.6,3201.75 ; 3631.92,3551.44 3622.87,3542.39 3622.87,3334.73 3640.89,3316.71 ; 4098.62,3221.52 4098.62,3304.76 ; 4873.32,1113.32 5013.68,1113.32 5046.66,1080.34 ; 5178.36,1577.17 5178.36,1648.9 5185.99,1656.54
  text "GND" at 5594.21,5071.21 h30
  text "GND" at 2288.75,5066.97 h30
  text "GND" at 570.04,5033.07 h30
  text "CONN_MONITOR_2" at 2473.41,4745.09 h35 r270
  text "4_PMIC_CLKOUT" at 3262.5,4696.64 h30
  text "3_DIG_SYNCOUT" at 3393.62,4647.48 h30 r270
  text "3_PMIC_CLKOUT" at 3502.68,4626.13 h30 r270
  text "4_DIG_SYNCOUT" at 2730.05,4612.04 h30 r270
  text "4_TDO" at 2622.58,4587.67 h35 r270
  text "3_TDO" at 3200.91,4495.54 h35 r270
  text "CONN_TP4" at 3547.79,3898.05 h35
  text "CONN_TP3" at 2991.13,3897.38 h35
  text "1_DIG_SYNCOUT" at 1680.5,3868.27 h30
  text "GND" at 188.34,3402.77 h30
  text "R" at 5601.76,2672.34 h30
  text "3_PMIC_CLKOUT" at 5815.62,2533.29 h30
  text "GND" at 6057.1,2437.86 h30
  text "PMIC2_TMPSNS_SCL" at 5819.52,2393.61 h30
  text "GND" at 1358.39,2324.2 h30
  text "PMIC2_TMPSNS_SDA" at 5819.66,2255.15 h30
  text "PMIC_BUCK_EN" at 5770.77,2131.18 h30
  text "Q" at 1507.19,1916.54 h30
  text "Q" at 315.74,1914.63 h30
  text "P" at 1886.62,1903.32 h30
  text "P" at 880.67,1866.26 h30
  text "PMIC_NRST" at 1656.03,1726.51 h30
  text "1_PMIC_CLKOUT" at 2195.12,1725.42 h30
  text "PMIC1_SCL" at 2135.41,1582.33 h30
  text "PMIC1_VANA" at 1673.26,1580.7 h30
  text "PMIC1_SDA" at 2142.9,1445.8 h30
  text "PMIC1_PGOOD" at 1666.63,1442.84 h30
  text "PMIC_BUCK_EN" at 2183.85,1304.05 h30
  text "PMIC1_GPIO2" at 1670.61,1302.33 h30
  text "CONN_TP1" at 3269.36,1205.83 h35
  text "CONN_TP2" at 3856.23,1181.59 h35
  text "CONN_MONITOR_1" at 2614.41,1146.35 h35
  text "GND" at 1346.62,1130.78 h30
  text "R" at 5753.36,1083.6 h30
  text "12XX_3_FMCW_CLKOUT" at 4728.12,1035.66 h30
  text "S" at 5257.82,988.51 h30
  text "2_TDO" at 3868.62,480.32 h35 r270
  text "1_TDO" at 3420.29,425.96 h35
  text "PMIC_NRST" at 4547.82,380.95 h30
  text "2_PMIC_CLKOUT" at 3700.98,357.6 h35
  text "2_DIG_SYNCOUT" at 4170.56,357.47 h35
  text "1_PMIC_CLKOUT" at 3155.4,352.81 h35
  text "GND" at 4778.55,318.04 h30
  text "PMIC2_VANA" at 4587.21,250.31 h30
  text "S" at 4678.84,211.3 h30
  text "PMIC2_PGOOD" at 4597.44,125.51 h30
  text "PMIC2_GPIO2" at 4593.35,-12.94 h30
  text ".Layer_Name" at 446,-989.49 h60
Top Paste:
  text ".Layer_Name" at 446,-989.49 h60
Bottom Paste:
  text ".Layer_Name" at 446,-989.49 h60
Top Solder:
  text ".Layer_Name" at 446,-989.49 h60
  text ".Layer_Name" at 446,-989.49 h60
Bottom Solder:
  text ".Layer_Name" at 446,-989.49 h60
Drill Guide:
  text ".Layer_Name" at 446,-989.49 h60
M1 Board Outline:
  the board outline again, w10
  text ".Layer_Name" at 445.07,-990.08 h60
M2 Board Dimensions:
  text ".Layer_Name" at 445.07,-990.08 h60
M3 3D STEP Top:
  text ".Layer_Name" at 446,-989.49 h60
M4 3D STEP Bottom:
  text ".Layer_Name" at 446,-989.49 h60
M5 Assembly Top:
  lines w5: 583.54,1762.96 583.54,2206.19 ; 5554.26,975.11 5554.26,1418.34
  lines w10: -423,-1061.17 6177,-1061.17 ; -423,-857.83 6179,-857.83 ; -423,-654.5 -423,-1264.5 3582,-1264.5 6179,-1264.5 6179,-654.5 -422.5,-654.5 -422.5,-1264.5 1153,-1264.5 ; 2042,-1264.5 2042,-654.5 ; 3309,-857.83 3309,-654.5 ; 4149,-857.83 4149,-654.5 ; 4771,-1271 4771,-1068.17
  text "COMPONENTS MARKED 'DNP' SHOULD NOT BE POPULATED." at 1022.5,-449.5 h60
  text "ASSEMBLY VARIANT:" at 1022,-565 h60
  text ".VariantName" at 2058,-565 h60
  text "PCB VIEWED FROM TOP SIDE" at -359.5,-786.67 h60
  text "BOARD #:" at 2117,-786.67 h60
  text ".PRJ_Number" at 2662.5,-786.67 h60
  text "REV:" at 3507,-786.67 h60
  text ".PCB_Rev" at 3798.5,-786.67 h60
  text "SVN REV:" at 4345,-786.67 h60
  text ".VersionControl_RevNumber" at 4851,-786.67 h60
  text "PLOT NAME =" at -359.5,-1195.34 h60
  text ".plot_File_Name" at 446,-1195.34 h60
  text "GENERATED    :" at 2119,-1195.34 h60
  text ".Print_Date" at 2988.5,-1195.34 h60
  text ".Print_Time" at 3717.5,-1195.34 h60
  text "TEXAS INSTRUMENTS" at 4982,-1195.34 h60
M6 Assembly Bottom:
  lines w10: -423.5,-858.33 6178.5,-858.33 ; -421.5,-1061.67 6178.5,-1061.67 ; 984.5,-1271.5 984.5,-1068.67 ; 1606.5,-858.33 1606.5,-655 ; 2446.5,-858.33 2446.5,-655 ; 3713.5,-1265 3713.5,-655 ; 4602.5,-1265 6178,-1265 6178,-655 -423.5,-655 -423.5,-1265 2173.5,-1265 6178.5,-1265 6178.5,-655
  text "COMPONENTS MARKED 'DNP' SHOULD NOT BE POPULATED." at 5971,-449 h60
  text ".VariantName" at 4927,-565 h60
  text "ASSEMBLY VARIANT:" at 5966,-565 h60
  text ".VersionControl_RevNumber" at 904.5,-787.17 h60
  text "SVN REV:" at 1410.5,-787.17 h60
  text ".PCB_Rev" at 1957,-787.17 h60
  text "REV:" at 2248.5,-787.17 h60
  text ".PRJ_Number" at 3093,-787.17 h60
  text "BOARD #:" at 3638.5,-787.17 h60
  text "PCB VIEWED FROM BOTTOM SIDE" at 6115,-787.17 h60
  text "TEXAS INSTRUMENTS" at 773.5,-1195.84 h60
  text ".Print_Time" at 2038,-1195.84 h60
  text ".Print_Date" at 2767,-1195.84 h60
  text "GENERATED    :" at 3636.5,-1195.84 h60
  text ".plot_File_Name" at 5309.5,-1195.84 h60
  text "PLOT NAME =" at 6115,-1195.84 h60
M9 Title Sheet:
  lines w5: -723.5,3435 -423.5,3435 ; -723.5,8435 -423.5,8435 ; 3276.5,-1565 3276.5,-1265 ; 3276.5,13135 3276.5,13435 ; 7276.5,-1565 7276.5,-1265 ; 7276.5,13135 7276.5,13435 ; 11276.5,-1565 11276.5,-1265 ; 11276.5,13135 11276.5,13435 ; 13076.5,-1265 14476.5,-1265 18976.5,-1265 ; 15276.5,-1565 15276.5,-1265 ; 15276.5,13135 15276.5,13435 ; 18976.5,-65 18976.5,-1265 ; 18976.5,3435 19276.5,3435 ; 18976.5,8435 19276.5,8435 ; 19276.5,-1265 19276.5,-1565 ; 18976.5,-1265 18976.5,13135 -423.5,13135 -423.5,-1265 18976.5,-1265 ; 19276.5,-1565 19276.5,13435 -723.5,13435 -723.5,-1565 19276.5,-1565
  lines w10: 10994,-1273.39 10994,-663.39 15976.5,-663.39 ; 15976.5,-1273.39 15976.5,-663.39 ; 15976.5,-963.39 18976.5,-963.39 ; 15976.5,-363.39 18976.5,-363.39 ; 15977.5,230.61 18977.5,230.61 ; 17481.5,-1263.39 17481.5,-663.39 ; 18976.5,-663.39 15976.5,-663.39 ; 18976.5,-63.39 15976.5,-63.39 ; 18981.5,731.11 15977.5,731.11 15976.5,731.11 15976.5,230.61 15976.5,-63.39 ; 15976.5,-663.39 15976.5,-63.39
  text "1" at 1258.5,13245 h70
  text "2" at 5253.5,13245 h70
  text "3" at 9248.5,13245 h70
  text "4" at 13249.51,13245 h70
  text "5" at 17247.84,13245 h70
  text "B" at -598.5,10847 h70
  text "B" at 19101.5,10847 h70
  text "C" at -598.5,5847 h70
  text "C" at 19101.5,5847 h70
  text "D" at -598.5,847 h70
  text "D" at 19101.5,847 h70
  text "PROJECT TITLE:" at 16016.5,137.61 h45
  text ".PRJ_Title" at 16066.5,4.28 h70
  text "DESIGNED FOR:" at 16016.5,-163.39 h45
  text ".PRJ_Customer" at 16066.5,-303.39 h70
  text "FILE NAME:" at 16016.5,-463.39 h45
  text ".PCB_File_Name_No_Path" at 16066.5,-583.39 h70
  text "Texas Instruments (TI) and/or its licensors do not warrant the accuracy or completeness of this specification" at 11047,-745.23 h45
  text "ENGINEER:" at 16016.5,-753.39 h45
  text "LAYOUT BY:" at 17521.5,-753.39 h45
  text "or any information contained therein. TI and/or its licensors do not warrant that this design will meet" at 11002.01,-857.89 h45
  text ".PRJ_Engineer" at 16066.5,-908.38 h70
  text ".PCB_Layout" at 17572,-908.38 h70
  text "the specifications, will be suitable for your application or fit for any particular purpose, or will operate in" at 11002.01,-970.56 h45
  text ".Layer_Name" at 445.07,-990.08 h60
  text "ALTIUM DESIGNER VERSION:" at 17521.5,-1063.39 h45
  text "an implementation. TI and/or its licensors do not warrant that the design is production worthy. You should" at 11002.01,-1083.22 h45
  text "completely validate and test your design implementation to confirm the system functionality for your application." at 11047,-1195.89 h45
  text ".print_Scale" at 16066.5,-1196.72 h70
  text ".Application_BuildNumber" at 17572,-1196.72 h70
  text "1" at 1258.5,-1450 h70
  text "2" at 5253.5,-1450 h70
  text "3" at 9248.5,-1450 h70
  text "4" at 13249.51,-1450 h70
  text "WO#307308-7306-D" at 16509.44,-1456.87 h70
  text "5" at 15928.92,-1461.99 h70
